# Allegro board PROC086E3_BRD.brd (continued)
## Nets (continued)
AOUT4_C: C197.1 R288.1 U33.6(-INB)
AOUT4_D: C199.1 R293.1 U33.5(+INB)
AOUT4_E: C199.2 R286.2 R289.1 R291.2
AOUT4_N: C202.2 TP65.1(TP) U32.26(VOUT4-)
AOUT4_O: C197.2 R287.2 R290.1 U33.7(OUTB)
AOUT4_P: C198.2 TP64.1(TP) U32.25(VOUT4+)
AOUT4N: C202.1 R295.1
AOUT4P: C198.1 R292.1
AOUT5_A: C362.1 R483.2 R484.1 R494.1 R496.2
AOUT5_B: C362.2 R492.1 R493.2 R494.2 R495.2
AOUT5_C: C360.1 R483.1 U56.2(-INA)
AOUT5_D: C363.1 R495.1 U56.3(+INA)
AOUT5_E: C363.2 R482.2 R487.1 R492.2
AOUT5_N: C364.2 U32.24(VOUT5-)
AOUT5_O: C360.2 R484.2 R488.1 U56.1(OUTA)
AOUT5_P: C361.2 U32.23(VOUT5+)
AOUT5N: C364.1 R496.1
AOUT5P: C361.1 R493.1
AOUT6_A: C370.1 R505.1 R507.2 R508.1 R509.2
AOUT6_B: C370.2 R502.1 R503.2 R505.2 R506.2
AOUT6_C: C367.1 R507.1 U56.6(-INB)
AOUT6_D: C371.1 R506.1 U56.5(+INB)
AOUT6_E: C371.2 R499.2 R501.1 R502.2
AOUT6_N: C372.2 U32.22(VOUT6-)
AOUT6_O: C367.2 R504.1 R508.2 U56.7(OUTB)
AOUT6_P: C368.2 U32.21(VOUT6+)
AOUT6N: C372.1 R509.1
AOUT6P: C368.1 R503.1
AOUT7_A: C187.1 R282.1 R283.1 R284.2 R285.2
AOUT7_B: C187.2 R275.1 R279.2 R281.2 R282.2
AOUT7_C: C184.1 R284.1 U31.2(-INA)
AOUT7_D: C186.1 R281.1 U31.3(+INA)
AOUT7_E: C186.2 R268.2 R273.1 R275.2
AOUT7_N: C189.2 TP66.1(TP) U32.20(VOUT7-)
AOUT7_O: C184.2 R280.1 R283.2 U31.1(OUTA)
AOUT7_P: C185.2 TP67.1(TP) U32.19(VOUT7+)
AOUT7N: C189.1 R285.1
AOUT7P: C185.1 R279.1
AOUT8_A: C173.1 R252.1 R253.2 R262.1 R265.2
AOUT8_B: C173.2 R258.1 R259.2 R261.2 R262.2
AOUT8_C: C169.1 R253.1 U31.6(-INB)
AOUT8_D: C172.1 R261.1 U31.5(+INB)
AOUT8_E: C172.2 R250.2 R254.1 R258.2
AOUT8_N: C177.2 TP69.1(TP) U32.18(VOUT8-)
AOUT8_O: C169.2 R252.2 R255.1 U31.7(OUTB)
AOUT8_P: C170.2 TP68.1(TP) U32.17(VOUT8+)
AOUT8N: C177.1 R265.1
AOUT8P: C170.1 R259.1
APP_BD_PORZ: J17.76 R486.1
AUD_REFCLK1_BUF: R122.2 U14.4(A2)
AUDEXP_INTB: J2.15 R103.2 TP123.1(TP) U15.22(I\N\T\)
AUDEXP_P16: TP54.1(TP) U15.16(P16)
AUDIO_EXT_REFCLK1: J1.26 R122.1 TP137.1(TP)
BIN1_N: C104.2 R172.2 R173.2 R179.2 TP71.1(TP) U19.51(VIN1-)
BIN1_P: C104.1 R184.2 R186.2 TP70.1(TP) U19.52(VIN1+)
BIN2_N: C120.2 R189.2 R191.2 R198.2 TP72.1(TP) U19.53(VIN2-)
BIN2_P: C120.1 R203.2 R204.2 TP73.1(TP) U19.54(VIN2+)
BIN3_N: C323.2 R429.2 R431.2 R439.2 U19.55(VIN3-)
BIN3_P: C323.1 R443.2 R444.2 U19.56(VIN3+)
BIN4_N: C308.2 R416.2 R417.2 R422.2 U19.57(VIN4-)
BIN4_P: C308.1 R426.2 R428.2 U19.58(VIN4+)
BIN5_N: C335.1 R452.2 R455.2 R456.2 TP76.1(TP) U19.61(VIN5-)
BIN5_P: C335.2 R450.2 R451.2 TP75.1(TP) U19.62(VIN5+)
BIN6_N: C125.1 R201.2 R202.2 R205.2 TP74.1(TP) U19.63(VIN6-)
BIN6_P: C125.2 R207.2 R209.2 TP77.1(TP) U19.64(VIN6+)
BISTEN: R7.1 U2.44(BISTEN)
BOUT1_A: C295.1 R395.2 R396.1 R401.1 R403.2
BOUT1_B: C295.2 R399.1 R400.2 R401.2 R402.2
BOUT1_C: C292.1 R395.1 U47.2(-INA)
BOUT1_D: C296.1 R402.1 U47.3(+INA)
BOUT1_E: C296.2 R392.2 R397.1 R399.2
BOUT1_N: C297.2 U19.32(VOUT1-)
BOUT1_O: C292.2 R396.2 R398.1 U47.1(OUTA)
BOUT1_P: C294.2 U19.31(VOUT1+)
BOUT1N: C297.1 R403.1
BOUT1P: C294.1 R400.1
BOUT2_A: C304.1 R410.1 R413.2 R414.1 R415.2
BOUT2_B: C304.2 R408.1 R409.2 R410.2 R411.2
BOUT2_C: C300.1 R413.1 U47.6(-INB)
BOUT2_D: C305.1 R411.1 U47.5(+INB)
BOUT2_E: C305.2 R405.2 R407.1 R408.2
BOUT2_N: C306.2 U19.30(VOUT2-)
BOUT2_O: C300.2 R412.1 R414.2 U47.7(OUTB)
BOUT2_P: C302.2 U19.29(VOUT2+)
BOUT2N: C306.1 R415.1
BOUT2P: C302.1 R409.1
BOUT3_A: C92.1 R164.1 R168.1 R169.2 R170.2
BOUT3_B: C92.2 R160.1 R162.2 R163.2 R164.2
BOUT3_C: C88.1 R169.1 U18.2(-INA)
BOUT3_D: C91.1 R163.1 U18.3(+INA)
BOUT3_E: C91.2 R153.2 R156.1 R160.2
BOUT3_N: C96.2 TP79.1(TP) U19.28(VOUT3-)
BOUT3_O: C88.2 R165.1 R168.2 U18.1(OUTA)
BOUT3_P: C90.2 TP78.1(TP) U19.27(VOUT3+)
BOUT3N: C96.1 R170.1
BOUT3P: C90.1 R162.1
BOUT4_A: C76.1 R140.1 R141.2 R149.1 R150.2
BOUT4_B: C76.2 R145.1 R147.2 R148.2 R149.2
BOUT4_C: C71.1 R141.1 U18.6(-INB)
BOUT4_D: C75.1 R148.1 U18.5(+INB)
BOUT4_E: C75.2 R139.2 R142.1 R145.2
BOUT4_N: C81.2 TP81.1(TP) U19.26(VOUT4-)
BOUT4_O: C71.2 R140.2 R143.1 U18.7(OUTB)
BOUT4_P: C73.2 TP80.1(TP) U19.25(VOUT4+)
BOUT4N: C81.1 R150.1
BOUT4P: C73.1 R147.1
BOUT5_A: C282.1 R369.2 R370.1 R377.1 R379.2
BOUT5_B: C282.2 R373.1 R375.2 R377.2 R378.2
BOUT5_C: C280.1 R369.1 U46.2(-INA)
BOUT5_D: C283.1 R378.1 U46.3(+INA)
BOUT5_E: C283.2 R368.2 R371.1 R373.2
BOUT5_N: C284.2 U19.24(VOUT5-)
BOUT5_O: C280.2 R370.2 R372.1 U46.1(OUTA)
BOUT5_P: C281.2 U19.23(VOUT5+)
BOUT5N: C284.1 R379.1
BOUT5P: C281.1 R375.1
BOUT6_A: C289.1 R387.1 R389.2 R390.1 R391.2
BOUT6_B: C289.2 R384.1 R385.2 R387.2 R388.2
BOUT6_C: C287.1 R389.1 U46.6(-INB)
BOUT6_D: C290.1 R388.1 U46.5(+INB)
BOUT6_E: C290.2 R381.2 R383.1 R384.2
BOUT6_N: C291.2 U19.22(VOUT6-)
BOUT6_O: C287.2 R386.1 R390.2 U46.7(OUTB)
BOUT6_P: C288.2 U19.21(VOUT6+)
BOUT6N: C291.1 R391.1
BOUT6P: C288.1 R385.1
BOUT7_A: C68.1 R135.1 R136.1 R137.2 R138.2
BOUT7_B: C68.2 R131.1 R132.2 R134.2 R135.2
BOUT7_C: C65.1 R137.1 U16.2(-INA)
BOUT7_D: C67.1 R134.1 U16.3(+INA)
BOUT7_E: C67.2 R127.2 R129.1 R131.2
BOUT7_N: C69.2 TP82.1(TP) U19.20(VOUT7-)
BOUT7_O: C65.2 R133.1 R136.2 U16.1(OUTA)
BOUT7_P: C66.2 TP83.1(TP) U19.19(VOUT7+)
BOUT7N: C69.1 R138.1
BOUT7P: C66.1 R132.1
BOUT8_A: C57.1 R106.1 R107.2 R115.1 R117.2
BOUT8_B: C57.2 R111.1 R113.2 R114.2 R115.2
BOUT8_C: C53.1 R107.1 U16.6(-INB)
BOUT8_D: C56.1 R114.1 U16.5(+INB)
BOUT8_E: C56.2 R105.2 R108.1 R111.2
BOUT8_N: C59.2 TP85.1(TP) U19.18(VOUT8-)
BOUT8_O: C53.2 R106.2 R109.1 U16.7(OUTB)
BOUT8_P: C55.2 TP84.1(TP) U19.17(VOUT8+)
BOUT8N: C59.1 R117.1
BOUT8P: C55.1 R113.1
BUF_VPFE0_DATA0: R37.2 U6.2(1B1) U6.13(2B1)
BUF_VPFE0_DATA1: R38.2 U6.3(1B2) U6.14(2B2)
BUF_VPFE0_DATA2: R33.2 U6.5(1B3) U6.16(2B3)
BUF_VPFE0_DATA3: R34.2 U6.6(1B4) U6.17(2B4)
BUF_VPFE0_DATA4: R39.2 U6.8(1B5) U6.19(2B5)
BUF_VPFE0_DATA5: R40.2 U6.9(1B6) U6.20(2B6)
BUF_VPFE0_DATA6: R35.2 U6.11(1B7) U6.22(2B7)
BUF_VPFE0_DATA7: R36.2 U6.12(1B8) U6.23(2B8)
BUF_VPFE0_DATA8: R45.2 U7.2(1B1) U7.13(2B1)
BUF_VPFE0_DATA9: R46.2 U7.3(1B2) U7.14(2B2)
BUF_VPFE0_DATA10: R41.2 U7.5(1B3) U7.16(2B3)
BUF_VPFE0_DATA11: R42.2 U7.6(1B4) U7.17(2B4)
BUF_VPFE0_DATA12: R532.2 U7.8(1B5)
BUF_VPFE0_DATA13: R533.2 U7.9(1B6)
BUF_VPFE0_HD: R43.2 U7.11(1B7) U7.22(2B7)
BUF_VPFE0_PCLK: R31.2 U5.11(2B1) U5.13(1B1)
BUF_VPFE0_VD: R44.2 U7.12(1B8) U7.23(2B8)
C_FPD_DOUT_N: C36.1 U8.19(DOUT-)
C_FPD_DOUT_P: C37.1 U8.20(DOUT+)
C_FPD_RIN_N: C17.1 U2.50(RIN-)
C_FPD_RIN_P: C16.1 U2.49(RIN+)
CAM_EXT_CLK: U35.2(1A) U35.5(2A) U38.3(OUTPUT)
CAM_I2C_SCL: J3.14 J6.29 R317.2 U36.3(SCL1)
CAM_I2C_SDA: J3.12 J6.30 R316.2 U36.4(SDA1)
CAM_LI_EXT_CLK: J6.7 R323.2
CAM_OV_EXT_CLK: J3.20 R315.2
CAM_SEL_LI#: U3.15(1\O\E\) U4.14(2\O\E\) U4.15(1\O\E\) U5.15(1\O\E\) U6.48(1O\E\) U7.48(1O\E\) U39.4(Y)
CAM_SEL_OV#: J1.91 TP135.1(TP) U3.14(2\O\E\) U5.14(2\O\E\) U6.25(2O\E\) U7.25(2O\E\) U39.2(A)
CAM_VIO_SEL: J2.20 U1.1(EN1)
CAPI2S: C24.1 U2.58(CAPI2S)
CAPL12: C26.1 C229.1 U2.4(CAPL12)
CAPP12: C23.1 U2.57(CAPP12)
CAPR12: C21.1 U2.55(CAPR12)
CDCE_1V8_I2C_SCL: R68.2 U9.3(SCL1) U42.12(SCL/S2)
CDCE_1V8_I2C_SDA: R69.2 U9.4(SDA1) U42.13(SDA/S1)
CDCE_PCLK: R22.2 R23.1 TP136.1(TP) U42.1(XIN/CLK)
CDCE_S0: R339.2 R342.1 U42.2(S0)
CDCE_VCTR: R54.2 U42.4(VCTR)
CDCE_Y1: R27.1 R63.1
CMC_FPD_DOUT_N: C36.2 FL5.2
CMC_FPD_DOUT_P: C37.2 FL5.1
CMC_FPD_RIN_N: C17.2 FL3.1
CMC_FPD_RIN_P: C16.2 FL3.2
CMF: C18.1 U2.51(CMF)
CODEC1_ACLKX: R188.2 U32.7(BCKAD) U32.36(BCKDA)
CODEC1_I2C_ADD0: R271.1 R272.2 U32.45(MS/ADR0/MD0)
CODEC1_I2C_ADD1: R277.1 R278.2 U32.44(MDO/ADR1/MD1)
CODEC1_MODE: R263.2 R264.2 U32.48(MODE)
CODEC1_OVF: TP13.1(TP) U32.5(OVF)
CODEC1_SCKI: R215.2 U32.41(SCKI)
CODEC1_VREFAD1: C157.1 U32.59(VREFAD1)
CODEC1_VREFAD2: C161.1 U32.60(VREFAD2)
CODEC1_ZERO: TP14.1(TP) U32.13(ZERO)
CODEC2_ACLKX: R187.2 U19.7(BCKAD) U19.36(BCKDA)
CODEC2_I2C_ADD0: R166.2 R167.1 U19.45(MS/ADR0/MD0)
CODEC2_I2C_ADD1: R158.2 R159.1 U19.44(MDO/ADR1/MD1)
CODEC2_MODE: R171.2 R174.2 U19.48(MODE)
CODEC2_OVF: TP3.1(TP) U19.5(OVF)
CODEC2_SCKI: R214.2 U19.41(SCKI)
CODEC2_VREFAD1: C312.1 U19.59(VREFAD1)
CODEC2_VREFAD2: C311.1 U19.60(VREFAD2)
CODEC2_ZERO: TP2.1(TP) U19.13(ZERO)
CODEC_RESETN: R498.1 TP102.1(TP) U15.1(P00) U19.4(RST#) U32.4(RST#)
CODEC_SCKI: J2.16 R538.1
CODECA_LIN_L: C332.2 J15.5B
CODECA_LIN_L_AC: C332.1 R449.1
CODECA_LIN_R: C134.2 J15.2B
CODECA_LIN_R_AC: C134.1 R210.1
CODECA_MIC1_L: J16.5B R227.1 R232.1
CODECA_MIC1_R: J16.2B R237.1 R245.1
CODECA_MIC2_L: J16.5A R470.1 R478.1
CODECA_MIC2_R: J16.2A R460.1 R467.1
CODECA_VOUT1: C373.2 J19.5B R520.1
CODECA_VOUT2: C380.2 J19.2B R522.1
CODECA_VOUT3: C204.2 J19.5A R300.1
CODECA_VOUT4: C196.2 J19.2A R296.1
CODECA_VOUT5: C359.2 J18.5B R497.1
CODECA_VOUT6: C366.2 J18.2B R500.1
CODECA_VOUT7: C183.2 J18.5A R269.1
CODECA_VOUT8: C168.2 J18.2A R266.1
CODECB_LIN_L: C338.2 J15.5A
CODECB_LIN_L_AC: C338.1 R457.1
CODECB_LIN_R: C122.2 J15.2A
CODECB_LIN_R_AC: C122.1 R200.1
CODECB_MIC1_L: J13.5B R178.1 R185.1
CODECB_MIC1_R: J13.2B R190.1 R197.1
CODECB_MIC2_L: J13.5A R430.1 R436.1
CODECB_MIC2_R: J13.2A R419.1 R427.1
CODECB_VOUT1: C293.2 J12.5B R404.1
CODECB_VOUT2: C301.2 J12.2B R406.1
CODECB_VOUT3: C89.2 J12.5A R155.1
CODECB_VOUT4: C72.2 J12.2A R151.1
CODECB_VOUT5: C279.2 J11.5B R380.1
CODECB_VOUT6: C286.2 J11.2B R382.1
CODECB_VOUT7: C64.2 J11.5A R128.1
CODECB_VOUT8: C52.2 J11.2A R118.1
CON_UB921_INTB: J1.87 R65.2
CON_VPFE0_DATA6: J1.22 U10.13(6A)
CON_VPFE0_DATA7: J1.24 U10.15(7A)
CON_VPFE0_DATA11: J1.56 U10.18(8A)
CON_VPFE0_DATA12: J1.54 U10.21(9A)
CONN_HDMI1_CEC: J4.13(CEC) U34.7(CEC_B)
CONN_HDMI1_CLK_N: FL19.3 J4.12(CLKN) U34.15(CLK-)
CONN_HDMI1_CLK_P: FL19.4 J4.10(CLKP) U34.16(CLK+)
CONN_HDMI1_HPD: J4.19(HPD) U34.10(HPD_B)
CONN_HDMI1_SCL: D1.1(CATHODE) J4.15(SCL) R319.2 U37.6(SCL2)
CONN_HDMI1_SDA: D2.1(CATHODE) J4.16(SDA) R320.2 U37.5(SDA2)
CONN_HDMI1_TXD0_N: FL18.3 J4.9(DATA0N) U34.17(D0-)
CONN_HDMI1_TXD0_P: FL18.4 J4.7(DATA0P) U34.18(D0+)
CONN_HDMI1_TXD1_N: FL17.3 J4.6(DATA1N) U34.20(D1-)
CONN_HDMI1_TXD1_P: FL17.4 J4.4(DATA1P) U34.21(D1+)
CONN_HDMI1_TXD2_N: FL16.3 J4.3(DATA2N) U34.22(D2-)
CONN_HDMI1_TXD2_P: FL16.4 J4.1(DATA2P) U34.23(D2+)
CT_HPD: R322.1 U34.12(CT_HPD)
DIR_AUDIO#: Q1.1(GATE) U45.1(A\U\D\I\O\)
DIR_BCKO: U14.17(B5) U14.18(B4) U45.11(BCKO)
DIR_BFRAME: TP47.1(TP) U45.18(BFRAME)
DIR_CKSEL: R351.2 R352.1 R355.2 TP111.1(TP) U15.11(P11) U45.28(CKSEL)
DIR_CLKST: TP48.1(TP) U45.9(CLKST)
DIR_COUT: TP50.1(TP) U45.15(COUT)
DIR_DOUT: U14.21(B1) U45.12(DOUT)
DIR_EMPH: Q3.1(GATE) U45.17(EMPH)
DIR_ERROR: Q2.1(GATE) R355.1 U45.27(ERROR)
DIR_FILT: C277.1 R101.1 U45.22(FILT)
DIR_FMT0: R97.2 R360.1 TP112.1(TP) U15.12(P12) U45.25(FMT0)
DIR_FMT1: R96.2 R357.1 TP113.1(TP) U15.13(P13) U45.26(FMT1)
DIR_JACK: C47.2 J8.2 R102.1
DIR_JACK_AC: C47.1 R100.2 U13.1(A)
DIR_LRCKO: U14.14(B8) U14.15(B7) U45.10(LRCKO)
DIR_PSCK0: R363.1 R365.2 TP114.1(TP) U15.14(P14) U45.13(PSCK0)
DIR_PSCK1: R364.1 R366.2 TP115.1(TP) U15.15(P15) U45.14(PSCK1)
DIR_RESETN: R98.2 TP110.1(TP) U15.10(P10) U45.21(R\S\T\)
DIR_RSV: R361.1 U45.19(RSV)
DIR_RXIN: SW1.2(COM) U45.20(RXIN)
DIR_RXIN_COAX: SW1.1 U13.4(Y)
DIR_SCKO: U14.20(B2) U45.4(SCKO)
DIR_UOUT: TP49.1(TP) U45.16(UOUT)
DIR_XTI: C276.1 U45.8(XTI) Y1.1
DIR_XTO: R359.1 U45.7(XTO)
DIT_GND: J9.1 J9.3 R116.2
DIT_JACK: J9.2 R104.2
DIT_JACK_AC: C51.1 R112.1 R119.2
EEPROM_A0: J2.19 R251.2 U30.1(A0)
EEPROM_A1: J2.21 R249.2 U30.2(A1)
EEPROM_A2: J2.23 R246.2 U30.3(A2)
EEPROM_WP: J2.25 R248.2 U30.7(WP)
EXP_3V3: J2.2 J2.4 J2.6 R260.2
EXP_DC_3V3: J17.57 J17.58 J17.59 J17.60 R473.2 R475.2
EXP_I2C1_SCL: J17.30 R218.2
EXP_I2C1_SDA: J17.28 R216.2
EXP_I2C2_SCL: J20.22 R310.2
EXP_I2C2_SDA: J20.21 R298.2
EXP_I2C4_SCL: J14.11 R434.2
EXP_I2C4_SDA: J14.12 R446.2
EXP_REFCLK: J2.22 TP11.1(TP)
EXP_RSTZ: J1.118 TP51.1(TP)
FPD_DE: TP141.1(TP) U8.5(DE) U10.7(3B3)
FPD_DOUT_N: FL5.3 J7.3
FPD_DOUT_P: FL5.4 J7.1
FPD_HSYNC: TP140.1(TP) U8.3(HS) U10.5(2B3)
FPD_PCLK: R22.1 R26.1 TP139.1(TP) U10.28(12B3)
FPD_RIN_N: FL3.4 J5.2
FPD_RIN_P: FL3.3 J5.4
FPD_VSYNC: TP142.1(TP) U8.4(VS) U10.10(4B3)
FSOUT0: TP42.1(TP) U45.2(FSOUT0)
FSOUT1: TP43.1(TP) U45.3(FSOUT1)
GPIO0_31: TP131.1(TP) U4.13(1B1) U11.31(11B2)
GPIO0_32: TP132.1(TP) U3.11(2B1) U3.12(1B2) U11.29(12B2)
HDMI1_CEC: TP25.1(TP) U34.1(CEC_A)
HDMI1_CLK_N: FL19.2 U41.21(TXC-)
HDMI1_CLK_P: FL19.1 U41.22(TXC+)
HDMI1_CTL1: R49.1 R343.2 U41.8(CTL1/A1/DK1)
HDMI1_CTL2: R52.1 R344.2 U41.7(CLT2/A2/DK2)
HDMI1_CTL3: R53.1 R345.2 U41.6(CLT3/A3/DK3)
HDMI1_DATA0: R72.2 U41.63(DATA0)
HDMI1_DATA0_R: R72.1 U11.54(1B1)
HDMI1_DATA1: R73.2 U41.62(DATA1)
HDMI1_DATA1_R: R73.1 U11.52(2B1)
HDMI1_DATA2: R74.2 U41.61(DATA2)
HDMI1_DATA2_R: R74.1 U11.50(3B1)
HDMI1_DATA3: R75.2 U41.60(DATA3)
HDMI1_DATA3_R: R75.1 U11.47(4B1)
HDMI1_DATA4: R76.2 U41.59(DATA4)
HDMI1_DATA4_R: R76.1 U11.45(5B1)
HDMI1_DATA5: R77.2 U41.58(DATA5)
HDMI1_DATA5_R: R77.1 U11.43(6B1)
HDMI1_DATA6: R78.2 U41.55(DATA6)
HDMI1_DATA6_R: R78.1 U11.41(7B1)
HDMI1_DATA7: R79.2 U41.54(DATA7)
HDMI1_DATA7_R: R79.1 U11.39(8B1)
HDMI1_DATA8: R80.2 U41.53(DATA8)
HDMI1_DATA8_R: R80.1 U11.36(9B1)
HDMI1_DATA9: R81.2 U41.52(DATA9)
HDMI1_DATA9_R: R81.1 U11.34(10B1)
HDMI1_DATA10: R82.2 U41.51(DATA10)
HDMI1_DATA10_R: R82.1 U11.32(11B1)
HDMI1_DATA11: R83.2 U41.50(DATA11)
HDMI1_DATA11_R: R83.1 U11.30(12B1)
HDMI1_DATA12: R84.2 U41.47(DATA12)
HDMI1_DATA12_R: R84.1 U12.54(1B1)
HDMI1_DATA13: R85.2 U41.46(DATA13)
HDMI1_DATA13_R: R85.1 U12.52(2B1)
HDMI1_DATA14: R86.2 U41.45(DATA14)
HDMI1_DATA14_R: R86.1 U12.50(3B1)
HDMI1_DATA15: R87.2 U41.44(DATA15)
HDMI1_DATA15_R: R87.1 U12.47(4B1)
HDMI1_DATA16: R88.2 U41.43(DATA16)
HDMI1_DATA16_R: R88.1 U12.45(5B1)
HDMI1_DATA17: R89.2 U41.42(DATA17)
HDMI1_DATA17_R: R89.1 U12.43(6B1)
HDMI1_DATA18: R90.2 U41.41(DATA18)
HDMI1_DATA18_R: R90.1 U12.41(7B1)
HDMI1_DATA19: R91.2 U41.40(DATA19)
HDMI1_DATA19_R: R91.1 U12.39(8B1)
HDMI1_DATA20: R92.2 U41.39(DATA20)
HDMI1_DATA20_R: R92.1 U12.36(9B1)
HDMI1_DATA21: R93.2 U41.38(DATA21)
HDMI1_DATA21_R: R93.1 U12.34(10B1)
HDMI1_DATA22: R94.2 U41.37(DATA22)
HDMI1_DATA22_R: R94.1 U12.32(11B1)
HDMI1_DATA23: R95.2 U41.36(DATA23)
HDMI1_DATA23_R: R95.1 U12.30(12B1)
HDMI1_DE: R61.2 TP36.1(TP) U41.2(DE)
HDMI1_DE_R: R61.1 U10.50(3B1)
HDMI1_DKEN: R29.2 R335.1 U41.35(DKEN)
HDMI1_HSYNC: R60.2 TP37.1(TP) U41.4(HSYNC)
HDMI1_HSYNC_R: R60.1 U10.52(2B1)
HDMI1_ISEL: C251.1 R32.2 R337.1 U41.13(ISEL/R\S\T\)
HDMI1_PCLK: R67.2 TP40.1(TP) U41.57(IDCK+)
HDMI1_PCLK_R: R67.1 U10.30(12B1)
HDMI1_TXD0_N: FL18.2 U41.24(TX0-)
HDMI1_TXD0_P: FL18.1 U41.25(TX0+)
HDMI1_TXD1_N: FL17.2 U41.27(TX1-)
HDMI1_TXD1_P: FL17.1 U41.28(TX1+)
HDMI1_TXD2_N: FL16.2 U41.30(TX2-)
HDMI1_TXD2_P: FL16.1 U41.31(TX2+)
HDMI1_VSYNC: R57.2 TP35.1(TP) U41.5(VSYNC)
HDMI1_VSYNC_R: R57.1 U10.47(4B1)
HDMI_BSEL: R25.1 R333.2 U41.15(BSEL/SCL)
HDMI_DDC_OE: R328.1 TP118.1(TP) U34.5(LS_OE) U37.8(EN) U43.11(P11)
HDMI_DSEL: R28.1 R334.2 U41.14(DSEL/SDA)
HDMI_EDGE: R48.1 R341.2 U41.9(EDGE/HTPLG)
HDMI_HPD: TP119.1(TP) U34.4(HPD_A) U43.12(P12)
HDMI_PDN: R340.2 TP117.1(TP) U41.10(P\D\) U43.10(P10)
HDMI_TFADJ: R21.2 U41.19(TFADJ)
HDMI_VREF: R346.1 U41.3(VREF)
I2C0_SCL: J1.109 TP55.1(TP)
I2C0_SDA: J1.111 TP56.1(TP)
I2C1_SCL: J1.113 R50.2 R376.2 TP133.1(TP) U8.8(SCL) U37.3(SCL1) U43.19(SCL)
I2C1_SDA: J1.115 R51.2 R374.2 TP134.1(TP) U8.9(SDA) U37.4(SDA1) U43.20(SDA)
I2C3_SCL: J2.8 R434.1 R491.1 TP129.1(TP) U2.3(SCL) U15.19(SCL) U19.42(MC/SCL/FMT) U32.42(MC/SCL/FMT)
I2C3_SDA: J2.10 R446.1 R485.1 TP130.1(TP) U2.2(SDA) U15.20(SDA) U19.43(MDI/SDA/DEMP) U32.43(MDI/SDA/DEMP)
I2C6_SCL: J2.107 R208.2 TP127.1(TP) U36.6(SCL2)
I2C6_SDA: J2.109 R206.2 TP128.1(TP) U36.5(SDA2)
I2S_CLK: R18.2 U2.1(GPO_REG8/I2S_CLK)
IDCK#: R58.1 U41.56(IDCK-)
IO_EXP_RESETN: R144.1 R146.1 TP138.1(TP) U15.24(R\E\S\E\T\) U43.24(R\E\S\E\T\)
JAMR3_GPIO0: J1.17 J14.33
JAMR3_GPIO1: J1.9 J14.34
JAMR3_GPIO2: J1.89 J14.35
JAMR3_I2S_CLK: J17.104 TP148.1(TP) U10.45(5B1)
JAMR3_I2S_DA: J17.103 TP150.1(TP) U10.34(10B1)
JAMR3_I2S_DB: J1.100 J17.105 TP151.1(TP)
JAMR3_I2S_WC: J17.102 TP149.1(TP) U10.32(11B1)
JAMR3_PWR_CTRL: R475.1 TP104.1(TP) U15.3(P02)
JAMR3_RESETN: J20.13 R297.1 TP103.1(TP) U15.2(P01)
LI_CAM_RST#: J6.33 R11.1 U3.5(1A2)
LI_CAM_TRIGGER: J6.35 R10.2 U4.4(1A1)
LI_SPI3_CLK: J6.32 U4.7(2A2)
LI_SPI3_CS0: J6.34 U4.6(2A1)
LI_SPI3_MISO: J6.31 U5.5(1A2)
LI_SPI3_MOSI: J6.36 U4.5(1A2)
LI_VIN_DATA0: J6.28 U6.47(1A1)
LI_VIN_DATA1: J6.27 U6.46(1A2)
LI_VIN_DATA2: J6.24 U6.44(1A3)
LI_VIN_DATA3: J6.23 U6.43(1A4)
LI_VIN_DATA4: J6.22 U6.41(1A5)
LI_VIN_DATA5: J6.21 U6.40(1A6)
LI_VIN_DATA6: J6.20 U6.38(1A7)
LI_VIN_DATA7: J6.19 U6.37(1A8)
LI_VIN_DATA8: J6.18 U7.47(1A1)
LI_VIN_DATA9: J6.17 U7.46(1A2)
LI_VIN_DATA10: J6.16 U7.44(1A3)
LI_VIN_DATA11: J6.15 U7.43(1A4)
LI_VIN_DATA12: J6.14 U7.41(1A5)
LI_VIN_DATA13: J6.13 U7.40(1A6)
LI_VIN_HD: J6.12 TP18.1(TP) U7.38(1A7)
LI_VIN_PCLK: R324.1 TP26.1(TP) U5.4(1A1)
LI_VIN_VD: J6.11 TP24.1(TP) U7.37(1A8)
LINA_L_A: C331.2 R447.1 U51.1(OUTA)
LINA_L_B: C331.1 R448.1 R449.2 U51.2(-INA)
LINA_L_C: C327.1 R441.1 R445.1 U51.6(-INB)
LINA_L_D: C327.2 R442.1 U51.7(OUTB)
LINA_R_A: C135.2 R212.1 U26.1(OUTA)
LINA_R_B: C135.1 R210.2 R211.1 U26.2(-INA)
LINA_R_C: C142.1 R217.1 R222.1 U26.6(-INB)
LINA_R_D: C142.2 R221.1 U26.7(OUTB)
LINB_L_A: C337.2 R455.1 U52.1(OUTA)
LINB_L_B: C337.1 R456.1 R457.2 U52.2(-INA)
LINB_L_C: C333.1 R450.1 R452.1 U52.6(-INB)
LINB_L_D: C333.2 R451.1 U52.7(OUTB)
LINB_R_A: C123.2 R202.1 U24.1(OUTA)
LINB_R_B: C123.1 R200.2 R201.1 U24.2(-INA)
LINB_R_C: C129.1 R205.1 R209.1 U24.6(-INB)
LINB_R_D: C129.2 R207.1 U24.7(OUTB)
MCASP0_ACLKX: J1.57 TP94.1(TP) U21.2(1A) U21.5(2A)
MCASP0_AFSX: J1.59 TP93.1(TP) U19.6(LRCKAD) U19.35(LRCKDA) U32.6(LRCKAD) U32.35(LRCKDA)
MCASP0_AXR0: J1.69 TP87.1(TP) U32.37(DIN1)
MCASP0_AXR1: J1.77 TP86.1(TP) U32.38(DIN2)
MCASP0_AXR2: J1.71 TP88.1(TP) U32.39(DIN3)
MCASP0_AXR3: J1.61 TP89.1(TP) U32.40(DIN4)
MCASP0_AXR4: J1.73 R270.2 TP90.1(TP)
MCASP0_AXR4_R: R270.1 U32.8(DOUT1)
MCASP0_AXR5: J1.53 R274.2 TP91.1(TP)
MCASP0_AXR5_R: R274.1 U32.9(DOUT2)
MCASP0_AXR6: J1.55 R276.2 TP92.1(TP)
MCASP0_AXR6_R: R276.1 U32.10(DOUT3)
MCASP0_AXR7: J1.72 TP95.1(TP) U19.37(DIN1)
MCASP0_AXR8: J1.70 TP96.1(TP) U19.38(DIN2)
MCASP0_AXR9: J1.78 TP97.1(TP) U19.39(DIN3)
MCASP0_AXR10: J1.76 TP98.1(TP) U19.40(DIN4)
MCASP0_AXR11: J1.74 R161.2 TP99.1(TP)
MCASP0_AXR11_R: R161.1 U19.8(DOUT1)
MCASP0_AXR12: J1.80 R157.2 TP100.1(TP)
MCASP0_AXR12_R: R157.1 U19.9(DOUT2)
MCASP0_AXR13: J1.102 R154.2 TP101.1(TP)
MCASP0_AXR13_R: R154.1 U19.10(DOUT3)
MCASP1_ACLKX: J1.110 R19.1 TP156.1(TP)
MCASP1_AFSX: J1.60 TP157.1(TP) U2.39(ROUT2/R2)
MCASP1_AXR0: J1.13 TP158.1(TP) U2.37(ROUT3/R3)
MCASP1_AXR1: J1.15 TP159.1(TP) U2.36(ROUT4/R4)
MCASP1_AXR2: J1.11 TP160.1(TP) U2.35(ROUT5/R5)
MCASP1_AXR3: J1.7 U2.34(ROUT6/R6)
MCASP1_AXR5: J2.7 U2.33(ROUT7/R7)
MCASP1_AXR6: J2.9 U2.26(ROUT10/G2)
MCASP1_AXR7: J1.85 U2.25(ROUT11/G3)
MCASP1_AXR8: J1.83 U2.23(ROUT12/G4)
MCASP2_AXR0: J1.93 R119.1
MCASP6_ACLKR: J1.92 R124.1
MCASP6_ACLKX: R123.1 U17.5(2B1)
MCASP6_AFSR: R126.1 R536.2
MCASP6_AFSX: R125.1 U17.11(3B1)
MCASP6_AXR0: R121.1 U17.2(1B1)
MCASP6_AXR1: TP1.1(TP) U17.14(4B1)
MCASP6_MUX_SEL: R130.2 TP116.1(TP) U15.17(P17) U17.1(S)
MCASP10_ACLKX/EHRPWM0_SYNCI: J2.41 J10.2
MCASP10_AFSX/EHRPWM0_SYNCO: J2.43 J10.3
MCASP10_AXR0/EHRPWM_TZN_IN0: J2.45 J10.4
MCASP10_AXR1/EHRPWM0_A: J2.47 J10.5
MCASP10_AXR2/EHRPWM1_B: J2.51 J10.6
MCASP10_AXR3/EHRPWM_TZN_IN1: J2.59 J10.1
MCASP11_ACLKX: J2.49 R235.2 TP143.1(TP)
MCASP11_AFSX: J2.53 R233.2 TP144.1(TP)
MCASP11_AXR0: J2.55 J17.37 TP145.1(TP)
MCASP11_AXR1: J2.61 J17.33 TP146.1(TP)
MCASP11_AXR2: J2.57 J17.39 TP147.1(TP)
MCASP11_AXR3: J2.63 J17.35
MCASP11_AXR4: J2.52 J17.23
MCASP11_AXR5: J2.42 J17.24
MCASP11_AXR6: J2.48 J17.22
MCASP11_AXR7: J2.44 J17.38
MCASP_ACLKR_BUF: R124.2 U14.7(A5)
MCASP_ACLKX_BUF: R123.2 U14.6(A4)
MCASP_AFSR_BUF: R126.2 U14.10(A8)
MCASP_AFSX_BUF: R125.2 U14.9(A7)
MCASP_AXR0_BUF: R121.2 U14.3(A1)
MIC1AL_A: C143.2 R219.1 U27.7(OUTB)
MIC1AL_AC: C147.1 R228.1
MIC1AL_B: C143.1 R220.1 R228.2 U27.6(-INB)
MIC1AL_BIAS: C151.2 R230.2 R232.2
MIC1AL_BIAS_AC: C148.1 C151.1 R229.1 U28.6(-INB)
MIC1AL_C: C150.1 R224.1 R231.1 U27.2(-INA)
MIC1AL_D: C150.2 R234.1 U27.1(OUTA)
MIC1AL_PRE: C148.2 R223.1 R229.2 U28.7(OUTB)
MIC1AR_A: C154.2 R236.1 U29.7(OUTB)
MIC1AR_AC: C158.1 R241.1
MIC1AR_B: C154.1 R238.1 R241.2 U29.6(-INB)
MIC1AR_BIAS: C153.2 R237.2 R239.2
MIC1AR_BIAS_AC: C153.1 C156.1 R240.1 U28.2(-INA)
MIC1AR_C: C163.1 R242.1 R256.1 U29.2(-INA)
MIC1AR_D: C163.2 R257.1 U29.1(OUTA)
MIC1AR_PRE: C156.2 R240.2 R247.1 U28.1(OUTA)
MIC1BL_A: C98.2 R172.1 U20.7(OUTB)
MIC1BL_AC: C105.1 R180.1
MIC1BL_B: C98.1 R173.1 R180.2 U20.6(-INB)
MIC1BL_BIAS: C111.2 R182.2 R185.2
MIC1BL_BIAS_AC: C106.1 C111.1 R181.1 U22.6(-INB)
MIC1BL_C: C108.1 R179.1 R184.1 U20.2(-INA)
MIC1BL_D: C108.2 R186.1 U20.1(OUTA)
MIC1BL_PRE: C106.2 R175.1 R181.2 U22.7(OUTB)
MIC1BR_A: C115.2 R189.1 U23.7(OUTB)
MIC1BR_AC: C118.1 R194.1
MIC1BR_B: C115.1 R191.1 R194.2 U23.6(-INB)
MIC1BR_BIAS: C114.2 R190.2 R192.2
MIC1BR_BIAS_AC: C114.1 C117.1 R193.1 U22.2(-INA)
MIC1BR_C: C121.1 R198.1 R203.1 U23.2(-INA)
MIC1BR_D: C121.2 R204.1 U23.1(OUTA)
MIC1BR_PRE: C117.2 R193.2 R199.1 U22.1(OUTA)
MIC2AL_A: C351.2 R469.1 U55.1(OUTA)
MIC2AL_AC: C354.1 R476.1
MIC2AL_B: C351.1 R471.1 R476.2 U55.2(-INA)
MIC2AL_BIAS: C350.2 R470.2 R472.2
MIC2AL_BIAS_AC: C350.1 C353.1 R474.1 U54.6(-INB)
MIC2AL_C: C358.1 R477.1 R489.1 U55.6(-INB)
MIC2AL_D: C358.2 R490.1 U55.7(OUTB)
MIC2AL_PRE: C353.2 R474.2 R481.1 U54.7(OUTB)
MIC2AR_A: C339.2 R453.1 U53.1(OUTA)
MIC2AR_AC: C342.1 R463.1
MIC2AR_B: C339.1 R454.1 R463.2 U53.2(-INA)
MIC2AR_BIAS: C347.2 R465.2 R467.2
MIC2AR_BIAS_AC: C343.1 C347.1 R464.1 U54.2(-INA)
MIC2AR_C: C345.1 R459.1 R466.1 U53.6(-INB)
MIC2AR_D: C345.2 R468.1 U53.7(OUTB)
MIC2AR_PRE: C343.2 R458.1 R464.2 U54.1(OUTA)
MIC2BL_A: C319.2 R429.1 U50.1(OUTA)
MIC2BL_AC: C322.1 R435.1
MIC2BL_B: C319.1 R431.1 R435.2 U50.2(-INA)
MIC2BL_BIAS: C318.2 R430.2 R432.2
MIC2BL_BIAS_AC: C318.1 C321.1 R433.1 U49.6(-INB)
MIC2BL_C: C326.1 R439.1 R443.1 U50.6(-INB)
MIC2BL_D: C326.2 R444.1 U50.7(OUTB)
MIC2BL_PRE: C321.2 R433.2 R440.1 U49.7(OUTB)
MIC2BR_A: C307.2 R416.1 U48.1(OUTA)
MIC2BR_AC: C310.1 R423.1
MIC2BR_B: C307.1 R417.1 R423.2 U48.2(-INA)
MIC2BR_BIAS: C316.2 R425.2 R427.2
MIC2BR_BIAS_AC: C313.1 C316.1 R424.1 U49.2(-INA)
MIC2BR_C: C315.1 R422.1 R426.1 U48.6(-INB)
MIC2BR_D: C315.2 R428.1 U48.7(OUTB)
MIC2BR_PRE: C313.2 R418.1 R424.2 U49.1(OUTA)
MODE_SEL: R16.1 R17.2 U2.15(MODE_SEL)
MUX_MCASP6_ACLKX: J1.84 TP153.1(TP) U17.7(2A)
MUX_MCASP6_AFSX: J1.88 TP154.1(TP) U17.9(3A)
MUX_MCASP6_AXR0: J1.94 TP152.1(TP) U17.4(1A)
MUX_MCASP6_AXR1: J1.90 TP155.1(TP) U17.12(4A)
OEN: R8.1 U2.31(OEN)
OSS_SEL: R6.1 U2.46(OSS_SEL)
OV_CAM_PWDN: R318.2 U3.6(2A1)
OV_VIN_DATA0: J3.26 U6.36(2A1)
OV_VIN_DATA1: J3.25 U6.35(2A2)
OV_VIN_DATA2: J3.24 U6.33(2A3)
OV_VIN_DATA3: J3.23 U6.32(2A4)
OV_VIN_DATA4: J3.2 U6.30(2A5)
OV_VIN_DATA5: J3.1 U6.29(2A6)
OV_VIN_DATA6: J3.4 U6.27(2A7)
OV_VIN_DATA7: J3.3 U6.26(2A8)
OV_VIN_DATA8: J3.6 U7.36(2A1)
OV_VIN_DATA9: J3.5 U7.35(2A2)
OV_VIN_DATA10: J3.8 U7.33(2A3)
OV_VIN_DATA11: J3.7 U7.32(2A4)
OV_VIN_HD: J3.13 TP16.1(TP) U7.27(2A7)
OV_VIN_PCLK: R312.1 TP17.1(TP) U5.6(2A1)
OV_VIN_PCLK_R: J3.17 R312.2
OV_VIN_VD: J3.15 TP15.1(TP) U7.26(2A8)
PCLK_R: R26.2 R27.2 U8.10(PCLK)
PERIPH_RSTZ: J2.28 R146.2
PWR_SW_UB921: R71.1 TP121.1(TP) U43.14(P14) U44.3(IN)
PWR_SW_UB926: R331.1 TP106.1(TP) U15.5(P04) U40.3(IN)
R_CDCE_Y1: R63.2 U42.11(Y1)
R_CODEC1_ACLKX: R188.1 U21.6(1Y)
R_CODEC1_SCKI: R215.1 U25.6(1Y)
R_CODEC2_ACLKX: R187.1 U21.3(2Y)
R_CODEC2_SCKI: R214.1 U25.3(2Y)
R_DIR_XTO: C267.1 R359.2 Y1.2
R_LI_VIN_PCLK: J6.9 R324.2
R_OV_CAM_PWDN: J3.10 R311.1 R313.2 R318.1
REFCLK0: R537.2 R539.1
REFCLK0/MCASP6_AFSR: J1.86 R536.1 R537.1
REFCLK0/REFCLK2: R538.2 R539.2 TP9.1(TP) U25.2(1A) U25.5(2A)
RESETSTATZ: J2.30 TP10.1(TP)
RXIN_OPTICAL: MOD1.3(VOUT) SW1.3
SHLD_GND_HDMI1: FL13.2 J4.20 J4.21 J4.22 J4.23
SOC_I2C2_SCL: J1.112 TP53.1(TP)
SOC_I2C2_SDA: J1.114 TP52.1(TP)
SOC_PORZ_OUT: J1.64 R144.2
SPI3_CLK: J1.105 U10.23(10A)
SPI3_CLK_MUX: U4.10(2B2) U10.33(10B2)
SPI3_CS0: J1.58 U4.11(2B1)
SPI3_D0: J1.101 U10.25(11A)
SPI3_D1: J1.103 U10.11(5A)
SPI3_MISO: U5.12(1B2) U10.44(5B2)
SPI3_MOSI: U4.12(1B2) U10.31(11B2)
U37_CL: R332.1 U40.13(CL)
U37_DIAG_EN: R330.1 U40.12(DIAG_EN)
U66_CL: R353.1 U44.13(CL)
U66_DIAG_EN: R349.1 U44.12(DIAG_EN)
UB921_DIN0: U8.43(GPO_REG4/B0/DIN16) U11.3(1B3)
UB921_DIN1: U8.44(GPO_REG5/B1/DIN17) U11.5(2B3)
UB921_DIN2: U8.45(B2/DIN18) U11.7(3B3)
UB921_DIN3: U8.46(B3/DIN19) U11.10(4B3)
UB921_DIN4: U8.47(B4/DIN20) U11.12(5B3)
UB921_DIN5: U8.48(B5/DIN21) U11.14(6B3)
UB921_DIN6: U8.1(B6/DIN22) U11.16(7B3)
UB921_DIN7: U8.2(B7/DIN23) U11.20(8B3)
UB921_DIN8: U8.35(DIN8/G0/GPIO2) U11.22(9B3)
UB921_DIN9: U8.36(DIN9/G1/GPIO3) U11.24(10B3)
UB921_DIN10: U8.37(G2/DIN10) U11.26(11B3)
UB921_DIN11: U8.38(G3 / DIN11) U11.28(12B3)
UB921_DIN12: U8.39(G4/DIN12) U12.3(1B3)
UB921_DIN13: U8.40(G5/DIN13) U12.5(2B3)
UB921_DIN14: U8.41(G6/DIN14) U12.7(3B3)
UB921_DIN15: U8.42(G7/DIN15) U12.10(4B3)
UB921_DIN16: U8.25(DIN0/R0/GPIO0) U12.12(5B3)
UB921_DIN17: U8.26(DIN1/R1/GPIO1) U12.14(6B3)
UB921_DIN18: U8.27(DIN2/R2) U12.16(7B3)
UB921_DIN19: U8.28(DIN3/R3) U12.20(8B3)
UB921_DIN20: U8.29(DIN4/R4) U12.22(9B3)
UB921_DIN21: U8.32(DIN5/R5) U12.24(10B3)
UB921_DIN22: U8.33(DIN6/R6) U12.26(11B3)
UB921_DIN23: U8.34(DIN7/R7) U12.28(12B3)
UB921_FSEL: R30.1 R336.1 U8.15(FSEL)
UB921_IDX: R20.2 R24.1 U8.6(IDX)
UB921_INTB: R66.2 TP122.1(TP) U43.15(P15)
UB921_INTB_R: R64.2 R65.1 R66.1 U8.31(INTB)
UB921_MODE_SEL: R62.2 R70.1 U8.24(MODE_SEL)
UB921_REM_INTB: TP31.1(TP) U8.16(REM_INTB)
UB921_RESETN: R55.2 TP120.1(TP) U8.21(PDB) U43.13(P13)
UB926_CMLOUTN: TP21.1(TP) U2.53(CMLOUTN)
UB926_CMLOUTP: TP23.1(TP) U2.52(CMLOUTP)
UB926_DE: TP29.1(TP) U2.6(DE)
UB926_GPIO1: J1.30 R535.1
UB926_GPIO2: J1.75 U2.28(ROUT8/G0/GPIO2)
UB926_GPIO3: J1.79 U2.27(ROUT9/G1/GPIO3)
UB926_GPIO_SPARE: R534.1 TP108.1(TP) U15.7(P06)
UB926_HS: TP28.1(TP) U2.8(HS)
UB926_I2S_CLK: R18.1 U17.6(2B2)
UB926_I2S_DA: U2.45(I2S_DA/GPO_REG6) U17.3(1B2)
UB926_I2S_DB: U2.18(ROUT17/B1/GPO_REG5/I2S_DB) U17.13(4B2)
UB926_I2S_WC: U2.30(I2S_WC/GPO_REG7) U17.10(3B2)
UB926_IDX: R13.2 R14.1 U2.56(IDX)
UB926_INTN: R15.1 U2.16(BISTC/INTB_IN)
UB926_LOCK: TP109.1(TP) U2.32(LOCK) U15.8(P07)
UB926_MCLK: TP27.1(TP) U2.60(MCLK)
UB926_PASS: TP19.1(TP) U2.42(PASS)
UB926_PCLK: R19.2 U2.5(PCLK)
UB926_RESETN: R329.1 TP105.1(TP) U2.59(PDB) U15.4(P03)
UB926_ROUT13: TP22.1(TP) U2.22(ROUT13/G5)
UB926_TUNER_RESET: R4.2 TP107.1(TP) U2.41(ROUT0/R0/GPIO0) U15.6(P05)
UB926_VS: TP30.1(TP) U2.7(VS)
V_DVDD: C33.1 C34.1 C243.1 C256.1 FL22.1 R59.1 R346.2 U41.1(DVDD1) U41.12(DVDD2) U41.33(DVDD3)
V_PVDD: C235.1 C237.1 C238.1 FL20.1 U41.18(PVDD)
V_TVDD: C30.1 C31.1 C242.1 FL21.1 R21.1 U41.23(TVDD1) U41.29(TVDD2)
VCOMAD1: C139.1 C145.1 C152.1 C159.1 C330.1 C341.1 C349.1 C356.1 C771.1 C772.1 C773.1 C774.1 R230.1 R239.1 R465.1 R472.1 U26.3(+INA) U26.5(+INB) U27.3(+INA) U27.5(+INB) U28.3(+INA) U28.5(+INB) U29.3(+INA) U29.5(+INB) U51.3(+INA) U51.5(+INB) U53.3(+INA) U53.5(+INB) U54.3(+INA) U54.5(+INB) U55.3(+INA) U55.5(+INB) U179.1(OUTA) U179.2(-INA)
VCOMAD1_CODEC: C171.1 U32.1(VCOMAD) U179.3(+INA) U179.5(+INB)
VCOMAD1_SPARE: TP171.1(TP) U179.6(-INB) U179.7(OUTB)
VCOMAD2: C103.1 C113.1 C119.1 C124.1 C309.1 C317.1 C324.1 C336.1 C767.1 C768.1 C769.1 C770.1 R182.1 R192.1 R425.1 R432.1 U20.3(+INA) U20.5(+INB) U22.3(+INA) U22.5(+INB) U23.3(+INA) U23.5(+INB) U24.3(+INA) U24.5(+INB) U48.3(+INA) U48.5(+INB) U49.3(+INA) U49.5(+INB) U50.3(+INA) U50.5(+INB) U52.3(+INA) U52.5(+INB) U180.1(OUTA) U180.2(-INA)
VCOMAD2_CODEC: C100.1 U19.1(VCOMAD) U180.3(+INA) U180.5(+INB)
VCOMAD2_SPARE: TP172.1(TP) U180.6(-INB) U180.7(OUTB)
VCOMDA1: C193.1 U32.15(VCOMDA)
VCOMDA2: C74.1 U19.15(VCOMDA)
VLDO_CAM_1V8: R2.1 U1.5(OUT2)
VLDO_CAM_3V3: R3.1 U1.6(OUT1)
VOUT0_DATA0: J1.39 U11.2(1A)
VOUT0_DATA1: J1.43 U11.4(2A)
VOUT0_DATA2: J1.41 U11.6(3A)
VOUT0_DATA3: J1.45 U11.9(4A)
VOUT0_DATA4: J1.47 U11.11(5A)
VOUT0_DATA5: J1.23 U11.13(6A)
VOUT0_DATA6: J1.49 U11.15(7A)
VOUT0_DATA7: J1.25 U11.18(8A)
VOUT0_DATA8: J1.27 U11.21(9A)
VOUT0_DATA9: J1.29 U11.23(10A)
VOUT0_DATA10: J1.31 U11.25(11A)
VOUT0_DATA11: J1.14 U11.27(12A)
VOUT0_DATA12: J1.18 U12.2(1A)
VOUT0_DATA13: J1.16 U12.4(2A)
VOUT0_DATA14: J1.10 U12.6(3A)
VOUT0_DATA15: J1.8 U12.9(4A)
VOUT0_DATA16: J1.42 U12.11(5A)
VOUT0_DATA17: J1.50 U12.13(6A)
VOUT0_DATA18: J1.46 U12.15(7A)
VOUT0_DATA19: J1.40 U12.18(8A)
VOUT0_DATA20: J1.44 U12.21(9A)
VOUT0_DATA21: J1.48 U12.23(10A)
VOUT0_DATA22: J1.28 U12.25(11A)
VOUT0_DATA23: J1.32 U12.27(12A)
VOUT0_DE: J1.34 U10.6(3A)
VOUT0_EXTPCLKIN: J1.21 U10.2(1A)
VOUT0_HSYNC: J1.12 U10.4(2A)
VOUT0_PCLK: J1.36 U10.27(12A)
VOUT0_VSYNC: J1.33 U10.9(4A)
VOUTEXP_INTB: J2.17 R354.2 TP124.1(TP) U43.22(I\N\T\)
VOUTEXP_P04: TP34.1(TP) U43.6(P05)
VOUTEXP_P05: TP33.1(TP) U43.7(P06)
VOUTEXP_P16: TP38.1(TP) U43.16(P16)
VOUTEXP_P17: TP39.1(TP) U43.17(P17)
VPFE0_DATA0: R37.1 U12.44(5B2)
VPFE0_DATA1: R38.1 U12.42(6B2)
VPFE0_DATA2: R33.1 U12.40(7B2)
VPFE0_DATA3: R34.1 U12.37(8B2)
VPFE0_DATA4: R39.1 U12.35(9B2)
VPFE0_DATA5: R40.1 U12.33(10B2)
VPFE0_DATA6: R35.1 U10.42(6B2)
VPFE0_DATA7: R36.1 U10.40(7B2)
VPFE0_DATA8: R45.1 U12.51(2B2)
VPFE0_DATA9: R46.1 U12.46(4B2)
VPFE0_DATA10: R41.1 U10.48(3B2)
VPFE0_DATA11: R42.1 U10.37(8B2)
VPFE0_DATA12: R532.1 U10.35(9B2)
VPFE0_DATA13: R533.1 U11.44(5B2)
VPFE0_HD: R43.1 U11.53(1B2)
VPFE0_PCLK: R31.1 U10.53(1B2)
VPFE0_VD: R44.1 U11.48(3B2)
VREF2_CAM: C219.1 R325.2 U36.7(VREF2) U36.8(EN)
VSYS_IO_3V3: J2.100 J2.102 J2.104 TP8.1(TP)
WKUP_I2C0_SCL: J1.65 R218.1 R393.1 U30.6(SCL)
WKUP_I2C0_SDA: J1.63 R216.1 R394.1 U30.5(SDA)
N19811491: C42.2 U8.23(CMF)
N19811520: R47.2 U8.18(RES1)
N19811540: C32.1 U8.14(CAPP12)
N19811568: C35.1 U8.17(CAPHS12)
N19811570: C28.1 C29.1 U8.7(CAPL12)
N23276319: R338.1 U41.11(MSEN/PO1)
N23670479: C204.1 R304.2
N23670482: C196.1 R290.2
N23684707: C278.1 R101.2
N23911217: J17.31 R233.1
N23911219: J17.29 R235.1
N23981776: C147.2 R226.2 R227.2
N23985739: C158.2 R244.2 R245.2
N23990208: R243.2 R244.1 R247.2
N23990244: R223.2 R225.2 R226.1
N24479449: C342.2 R460.2 R461.2
N24479767: R458.2 R461.1 R462.2
N24480253: R479.1 R480.2 R481.2
N24480259: C354.2 R478.2 R479.2
N24488350: C373.1 R514.2
N24488546: C380.1 R526.2
N24492127: C183.1 R280.2
N24492135: C359.1 R488.2
N24492520: C168.1 R255.2
N24492543: C366.1 R504.2
N24497380: C118.2 R196.2 R197.2
N24497698: R195.2 R196.1 R199.2
N24498184: R175.2 R176.2 R177.1
N24498190: C105.2 R177.2 R178.2
N24501627: C310.2 R419.2 R420.2
N24501939: R418.2 R420.1 R421.2
N24502423: R437.1 R438.2 R440.2
N24502429: C322.2 R436.2 R437.2
N24516386: C89.1 R165.2
N24516394: C293.1 R398.2
N24516779: C72.1 R143.2
N24516802: C301.1 R412.2
N24517434: C64.1 R133.2
N24517442: C279.1 R372.2
N24517839: C52.1 R109.2
N24517862: C286.1 R386.2
N24561941: R50.1 U9.6(SCL2)
N24561944: R51.1 U9.5(SDA2)
N24562809: C38.1 R56.2 U9.7(VREF2) U9.8(EN)
N24589481: R5.2 R534.2 R535.2 U2.40(ROUT1/R1/GPIO1)
N24613389: R110.2 U15.18(ADDR)
N24636980: R315.1 U35.6(1Y)
N24637007: R323.1 U35.3(2Y)
N24638437: R326.2 U38.1(STANDBY)
N24673543: TP44.1(TP) U11.37(8B2)
N24673545: TP45.1(TP) U11.40(7B2)
N24673547: TP46.1(TP) U11.51(2B2)
N24676160: TP41.1(TP) U10.3(1B3)
N24676162: TP32.1(TP) U10.54(1B1)
N24733661: R314.1 U35.7(\\2\\\O\\\E)
N24733666: R321.1 U35.1(\\1\\\O\\E)
N24736802: R120.2 U14.2(DIR)
N24788879: C217.1 R327.1 U37.7(VREF2)
N24793440: R213.1 U25.1(\\1\\\O\\E) U25.7(\\2\\\O\\\E)
N24805264: R347.2 U43.18(ADDR)
N24817584: R183.1 U21.1(\\1\\\O\\E) U21.7(\\2\\\O\\\E)
N24985508: R99.1 R100.1 U13.3(A) U13.6(Y)
N24986462: C51.2 R104.1
N24987908: LD2.2 R358.2
N24987961: LD2.1 Q2.3(DRAIN)
N24990777: LD3.2 R367.2
N24990859: LD3.1 Q3.3(DRAIN)
N24990930: LD1.2 R350.2
N24990935: LD1.1 Q1.3(DRAIN)

Pads without a net: J1 35 62 66 97 98 99 104 106 116 117; J2 11 12 13 14 18 24 26 27 29 31 33 35 36 37 38 46 50 54 56 58 60 62 64 65 66 69 70 71 72 73 74 75 76 83 84 85 86 87 88 89 90 91 92 93 94 95 96 97 98 99 101 103 106 108 110 111 112 113 115 117; J3 9 11 27 28 29 30; J4 14 17; J10 7; J14 1 3 5 6 7 8 9 13 14 15 16 17 18 21 22 23 24 25 26 27 28 31 32 36 37 38; J17 1 2 3 4 5 6 7 8 9 10 11 12 13 14 15 16 17 18 19 20 21 25 32 34 36 40 41 42 43 44 45 46 47 48 55 56 61 62 63 64 65 66 67 68 69 70 71 72 73 74 75 79 80 81 82 83 84 85 86 87 88 89 90 91 92 93 94 95 96 97 98 99 100 101 106 107 108 109 110 111 112 113 114 117 118 119 120; J20 1 2 3 4 5 6 7 8 9 10 11 12 14 15 16 17 18 23 24 25 26 27 28 29 30 31 32 33 34 35 36 37 38 39 40; MOD1 4 5; U2 9 10 11 12 14 17 19 20 21; U3 4 7; U5 10; U7 19 20; U8 11 12 13; U10 12 14 16 20 22 24 26 29 36 39 41 43 46 51; U11 33 35 42 46; U12 29 31 48 53; U14 5 8; U34 2 3 8 9; U39 1; U40 1 4 11 14; U41 49; U42 8 9 14; U43 1 2 3 4 5 8; U44 1 4 11 14

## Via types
v1: diameter 0.457, hole 0.203, TOP to BOTTOM, 1815 vias

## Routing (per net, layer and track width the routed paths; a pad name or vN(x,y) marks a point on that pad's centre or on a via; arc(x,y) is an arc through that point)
DGND: length 781.7
  TOP w0.203: J1.126 89.14,119.51 J1.82 ; J2.1 84.01,45.13 v1(83.36,44.48) ; U6.39 v1(55.74,172.69) ; v1(94.77,103.64) 94.59,103.46 91.35,103.46 J1.38 ; v1(94.39,66.94) 94.26,67.06 92.94,67.06 92.51,66.63 J2.68 ; U7.10 67.05,168.98 66.8,169.22 v1(66.8,169.27) ; J1.5 85.09,95.46 83.44,95.46 v1(83.21,95.23) 83.21,95.21 83.41,95.01 J1.3 ; J1.108 92.24,126.01 92.48,125.76 v1(93.09,125.76) ; U3.2 U3.3 v1(39.69,174.95) ; U7.28 v1(71.45,172.69) ; v1(81.23,68.23) 83.24,68.23 84.14,69.13 J2.77 ; v1(44.9,174.95) U4.2 U4.3 ; v1(87.1,120.51) 86.1,119.51 J1.81 ; U6.10 55.74,169.08 v1(56.14,169.48) ; J1.52 93.18,107.01 94.54,108.36 v1(94.54,108.92) ; J2.40 89.64,54.63 89.13,54.13 v1(89.13,52.53) ; J1.1 v1(82.94,94.51) ; v1(79.31,142.86) 79.78,142.39 U11.19 ; J1.96 89.6,123.01 89.43,123.17 v1(89.43,124.95) ; v1(41.17,166.99) 42.3,166.99 42.5,167.19 U4.9 ; J1.95 86.32,123.01 86.8,123.49 v1(86.8,124.7) ; U3.8 v1(37.69,174.95) ; v1(82.78,98.53) 83.21,98.97 85.1,98.97 J1.19 ; J2.67 84.18,66.63 83.41,67.39 v1(81.28,67.39) ; v1(88.14,108.09) 87.06,107.01 J1.51 ; v1(52.93,170.47) 53.34,170.06 U6.4 ; U1.4 61.55,195.21 ; v1(94.36,142.16) 94.63,142.16 95.22,141.57 U12.19 ; v1(22.04,180.23) 21.54,179.73 U2.54 ; v1(48.41,99.55) 49.09,100.23 U19.50 ; v1(74.53,142.48) 74.28,142.22 U11.8 ; J2.123 87.29,54.63 J2.39 ; v1(63.87,150.61) 64.21,150.27 U10.38 ; v1(90.6,81.85) 91.3,81.15 J2.120 ; U6.21 v1(60.14,169.15) ; U7.4 v1(64.65,169.15) ; U4.8 42.5,174.85 v1(42.4,174.95) ; v1(38.1,170.24) 37.54,169.68 37.54,169.22 37.64,169.12 37.64,168.07 U3.9 ; U2.43 22.08,182.81 v1(22.04,182.77) 21.58,183.23 U2.47 ; J1.120 89.78,129.01 v1(89.51,128.74) ; J2.119 83.95,79.63 v1(83.57,80.02) ; U7.45 v1(64.65,172.69) ; U15.9 58.76,131.13 v1(59.01,130.88) ; U6.28 v1(60.14,172.69) ; U11.38 v1(79.78,149.41) ; 87.38,118.63 87.38,116.7 86.69,116.01 J1.67 ; U12.49 v1(89.72,146.1) ; v1(79.81,71.08) 82.98,71.08 83.93,70.13 J2.81 J2.79 ; J1.37 v1(86.7,103.51) ; U19.2 57.17,103.89 ; J2.105 84.25,76.13 v1(83.74,75.62) ; v1(82.42,44.81) 83.24,45.63 J2.3 ; v1(89.48,114.13) 89.48,115.6 89.89,116.01 J1.68 ; U10.19 64.19,140.71 v1(64.19,141.82) ; v1(89.92,143.75) 89.92,141.97 89.72,141.77 U12.8 ; U7.39 v1(67.05,172.69) ; U7.15 v1(69.05,169.15) ; v1(74.57,146.77) 74.48,146.87 74.48,147.02 74.28,147.23 U11.49 ; v1(71.12,169.27) 71.24,169.27 71.45,169.07 U7.21 ; U5.9 v1(47.32,166.89) ; U6.45 v1(53.34,172.69) ; U7.34 v1(69.05,172.69) ; U6.34 v1(57.74,172.69) ; v1(47.22,174.99) 47.22,174.96 47.29,174.89 47.29,173.85 U5.8 ; J1.107 86.22,126.01 v1(86.66,125.56) ; U6.15 v1(57.74,169.15) ; J1.119 v1(85.14,129.85) ; v1(95.22,149.41) U12.38 ; v1(95.02,100.82) 95.02,100.44 93.55,98.97 91.34,98.97 J1.20 ; v1(81.86,46.62) 82.35,46.13 J2.5
  TOP w0.254: v1(55.52,143.29) 58.17,143.29 58.71,142.74 U10.8 ; v1(49.8,104.6) 49.09,103.89 U19.47 ; v1(54.88,104.6) 56.46,104.6 57.17,103.89 ; U32.50 55.59,55.08 v1(56.35,55.84) ; U10.49 58.71,147.33 60.19,145.86 v1(61.49,145.86) ; U32.16 v1(46.64,40.33) ; v1(54.88,108.41) 54.9,108.39 U19.11 ; U19.16 v1(58.04,112.03) ; v1(49.8,43.41) 49.78,43.43 U32.11 ; U32.47 55.59,47.93 v1(54.88,47.22) ; U32.2 45.69,47.93 45.44,48.19 v1(45.44,48.92) ; U19.33 v1(46.64,112.03) ; U32.33 58.04,40.7
  TOP w0.305: 41.81,134.48 41.83,134.45 C277.2
  TOP w0.381: R70.2 v1(28.44,154.12) ; v1(45.32,126.43) C61.2 v1(46.42,125.58) ; C23.2 v1(14.56,176.75) 13.78,176.75 R14.2 ; C180.2 v1(63.94,49.03) ; C182.2 v1(66.32,49.03) ; v1(94.59,42.55) 94.59,43.09 95.22,43.72 C176.2 96.6,43.72 96.98,43.34 v1(96.98,42.58) ; R296.2 v1(13.59,27.51) ; v1(28.4,188.92) 28.4,187.54 C9.2 ; v1(48.7,183.5) C15.2 v1(46.48,182.84) ; R273.2 v1(23.53,39.6) ; v1(65.46,195.93) C2.2 v1(64.47,196.59) ; C312.2 v1(51.76,91.42) ; C97.2 v1(65.41,100.24) ; C195.2 v1(64.02,35.69) ; C103.2 v1(36.46,94.53) ; v1(31.17,152.1) 30.63,152.64 C44.2 ; R48.2 79.22,162.21 79.46,161.97 79.46,161.44 79.22,161.2 R52.2 79.22,160.31 v1(79.5,160.03) ; v1(88.52,166.93) 89.04,167.45 C30.2 ; R266.2 v1(13.39,43.76) ; J1.121 v1(88.92,93.32) ; v1(52.58,147.73) 47.6,147.73 46.74,146.87 46.74,142.48 v1(46.55,142.29) ; C49.2 v1(45.05,133.88) ; J2.128 v1(88.22,82.48) ; v1(28.5,153.27) 29.22,153.99 C43.2 ; C128.2 94.17,76.86 v1(94.39,76.64) ; U17.8 65.28,121.33 v1(64.77,121.84) ; C34.2 85.5,164.87 v1(85.98,164.39) ; R289.2 v1(23.47,31.72) ; C162.2 v1(68.28,49.1) ; U23.4 v1(35.75,82.86) ; C58.2 v1(16.03,125.74) ; C165.2 v1(56.35,54.82) ; R301.2 v1(24.91,23.09) ; C40.2 v1(20.49,159.43) ; C210.2 v1(18.19,197.77) ; C220.2 90.85,181.03 91.06,181.24 91.06,182.84 v1(90.85,183.05) ; C32.2 v1(22.09,166.97) ; C83.2 v1(60.85,112.53) ; U14.16 v1(53.36,134.98) ; 58.04,40.7 v1(58.04,40.33) ; C99.2 v1(30.56,98.57) ; C6.2 87.37,190.41 86.99,190.03 v1(86.08,190.03) ; U31.4 21.07,40.36 v1(21.08,40.37) ; R96.1 R97.1 42.68,144.01 v1(42.42,143.75) ; C38.2 41.86,158.71 v1(41.86,157.56) ; C110.2 95.94,91.88 v1(95.81,91.75) ; C62.2 v1(40.16,125.62) ; v1(60.85,113.55) 62.03,112.37 C84.2 ; v1(18.3,186.33) C12.2 v1(17.22,185.48) ; R47.1 v1(22.01,162.71) ; C161.2 v1(42.04,55.33) ; v1(21.11,24.01) 21.09,24.03 U33.4 ; v1(92.33,166.93) 92.04,167.22 C31.2 ; J1.125 v1(88.92,113.32) ; C5.2 v1(70.74,190.76) ; v1(86.8,124.7) 87.05,124.94 J1.127 ; C100.2 v1(60.52,99.3) ; v1(14.91,185.52) C14.2 v1(14,184.86) ; C203.2 v1(13.59,26.28) ; R263.1 v1(59.49,51.22) ; C166.2 v1(57.59,54.82) ; v1(28.12,106.28) 28.1,106.3 U18.4 ; C152.2 v1(26.24,57.45) ; C193.2 v1(42.06,38.83) ; C145.2 v1(36.46,63.9) ; C192.2 v1(58.94,39.02) ; v1(21.26,122.03) 21.25,122.04 U16.4 ; C45.2 v1(26.52,142.45) ; C167.2 v1(62.35,54.01) ; U27.4 v1(35.75,60.54) ; U20.4 v1(35.75,93.47) ; v1(51.97,181.21) 52.92,182.16 R10.1 ; R59.2 81.88,156.93 v1(81.9,156.91) ; C174.2 v1(97.6,43.68) ; C190.2 v1(42.56,40.33) ; J2.122 v1(88.22,51.94) ; R297.2 v1(60.93,23.53) ; J1.128 v1(87.52,130.21) ; v1(22.1,171.43) 22.99,172.32 C25.2 ; C127.2 v1(95.68,77.35) ; R174.1 v1(42.98,102.2) ; R328.2 v1(94.75,181.55) ; C107.2 v1(18.76,93.78) ; C86.2 v1(69.83,106.31) ; R300.2 v1(13.59,25.1) ; C102.2 v1(47.16,98.33) ; C194.2 v1(58.13,37.33) ; R58.2 90.04,159.06 v1(89.79,159.31) ; J2.121 v1(88.22,42.29) ; J1.122 v1(88.92,98.59) ; C119.2 v1(36.46,83.93) ; v1(9.91,133.84) 10.52,133.84 C50.2 10.57,132.7 v1(9.91,132.7) ; v1(42.48,41.26) 42.86,41.64 C188.2 ; v1(79.83,167.57) 79.83,166.91 79.48,166.56 R28.2 ; v1(54.22,76.07) C131.2 v1(53.04,76.92) ; C42.1 v1(25.4,155.43) ; C8.2 v1(29.13,174.48) ; C1.2 v1(55.07,196.46) ; R272.1 v1(63.94,46.49) ; U29.4 v1(35.75,49.94) ; C20.2 v1(30.94,178.24) ; R108.2 v1(23.6,129.74) ; J2.123 v1(88.22,58.29) J2.124 ; C175.2 v1(16.03,44.06) ; v1(38.67,126.43) C60.2 v1(37.58,125.58) ; R142.2 v1(30.52,114) ; R120.1 v1(47.52,123.57) ; R112.2 v1(74.47,127.69) ; R53.2 R49.2 75.98,161.72 v1(75.69,161.43) ; v1(18.88,155.1) C39.2 18.88,157.94 v1(18.87,157.95) ; R278.1 v1(63.91,42.04) ; C149.2 v1(18.76,60.85) ; U14.12 v1(55.92,128.08) ; C26.2 20.02,173.68 v1(20.02,173.67) ; v1(69.72,114.26) 69.41,114.57 U17.15 ; J2.127 v1(88.22,78.29) ; v1(42.57,155.53) 42.93,155.89 U9.1 ; R130.1 72.18,122.32 v1(72.34,122.49) ; C164.2 v1(58.96,54.82) ; C10.2 v1(69.7,187.88) ; v1(26.39,136.3) 26.2,136.49 U13.2 ; C24.2 v1(14.53,174.97) ; C21.2 v1(14.56,178.81) ; J2.126 v1(88.22,72.45) ; v1(58.12,196.51) R1.1 v1(58.99,195.85) ; C178.2 v1(43.25,49.58) ; C181.2 v1(61.39,48.41) ; C18.2 v1(15.61,180.24) ; C27.2 v1(30.63,171.86) ; C95.2 v1(62.38,100.68) ; C35.2 v1(21.19,164.17) ; C46.2 v1(7.38,136.1) ; R166.1 v1(41.58,104.25) ; J1.123 v1(88.92,104.94) ; v1(12.47,152.64) 12.47,152.63 R71.2 ; R5.1 v1(24.08,188.92) ; U14.11 v1(54.66,126.97) ; v1(45.43,76.07) C130.2 v1(46.6,76.92) ; C211.2 v1(16.81,197.77) ; C116.2 v1(30.56,87.96) ; C191.2 v1(58.94,40.33) ; C201.2 v1(16.03,27.73) ; C70.2 v1(72.37,116.65) ; C87.2 v1(66.27,106.31) ; 93.92,90.9 93.22,90.2 v1(93.22,89.57) ; C336.2 v1(25.51,71.21) ; C33.2 93.66,166.87 v1(93.6,166.93) ; R151.2 v1(13.26,108.88) ; 32.01,70.35 C328.2 32.98,70.35 v1(33.45,70.82) ; C48.2 v1(45.06,135.11) ; U14.22 v1(49.46,134.98) ; C74.2 v1(59.77,115.52) ; U30.4 v1(78.14,52.91) ; C138.2 v1(95.47,72.44) ; C144.2 v1(30.56,65.64) ; C101.2 v1(45.92,98.33) ; v1(68.34,189.4) C3.2 v1(67.25,190.32) ; C93.2 v1(60.89,101.49) ; v1(87.32,118.68) 87.42,118.59 J1.126 ; C159.2 v1(36.46,53.29) ; U52.4 v1(15.32,77.15) ; v1(45.67,143.26) 45.41,143.52 R98.1 ; R23.2 v1(29.01,168.19) ; J2.125 v1(88.22,65.59) ; C132.2 v1(48.03,76.24) ; C29.2 v1(32.14,171.05) ; U22.4 v1(23.97,88.17) ; C79.2 v1(43.56,112.53) ; R254.2 v1(23.6,48.06) ; R116.1 v1(74.47,126.73) ; R99.2 v1(25.27,142.46) ; R25.2 v1(77.32,166.2) ; R156.2 v1(32.75,105.23) ; C28.2 v1(30.4,171.05) ; R128.2 v1(13.34,123.19) ; R129.2 v1(26.11,120.54) ; J1.124 v1(88.92,110.21) ; C179.2 v1(44.5,49.58) ; U24.4 v1(27.22,74.75) ; C334.2 v1(20.39,72.05) ; C133.2 v1(51.48,76.24) ; C82.2 v1(63.53,113.55) ; R155.2 v1(13.26,106.62) ; 61.55,195.21 v1(61.55,195.98) ; R4.1 v1(22.8,188.92) ; C85.2 v1(21.08,105.73) ; C94.2 v1(59.71,101.48) ; C113.2 v1(26.24,90.37) ; C157.2 v1(42.04,57.01) ; C7.2 v1(70.25,189.33) ; v1(63.35,190.36) C4.2 v1(65.86,190.36) ; C63.2 v1(43.71,125.62) ; C155.2 v1(30.56,55.04) ; C77.2 v1(65.79,113.28) ; R158.1 v1(41.58,108.72) ; C171.2 v1(45.02,53.7) ; R269.2 v1(13.34,41.51) ; R24.2 v1(35.23,168.35) ; U14.19 v1(51.41,134.98) ; C311.2 v1(53.51,91.42) ; R55.1 v1(22.51,159.32) ; C13.2 v1(31.44,185.56) ; C41.2 v1(23.89,155.37) ; C124.2 v1(13.63,74.25) ; C137.2 v1(93.85,73.33) ; U14.13 v1(55.31,132.44) ; R118.2 v1(13.34,125.44) ; C80.2 v1(44.72,112.53) ; C212.2 v1(14.17,197.54) ; C54.2 v1(45.71,127.38) ; U28.4 v1(23.97,55.25)
  TOP w0.508: C22.2 v1(75.38,176.77) ; C19.2 v1(75.82,180.38)
  BOTTOM w0.203: U35.4 v1(36.25,182.35) ; U21.4 65.91,95.11 v1(66.23,94.79) ; v1(93.6,165.66) 94.31,166.37 U41.34 ; v1(64.83,72.25) 64.33,71.74 U25.4 ; v1(93.6,166.93) 93.54,166.99 U41.32 ; U41.16 85.92,166.87 v1(85.98,166.93) 86.04,166.99 U41.17 ; U41.26 90.54,167.45 v1(91.06,166.93) ; U41.20 87.54,167.22 v1(87.25,166.93) ; v1(66.62,159.39) 66.75,159.27 U43.9 ; v1(85.98,159.31) 86.04,159.25 U41.64 ; U41.48 93.66,159.37 v1(93.6,159.31)
  BOTTOM w0.254: J4.5 v1(94.85,189.71) ; J4.2 v1(96.35,189.71) ; J4.8 v1(93.35,189.71) ; J4.11 v1(91.85,189.71)
  BOTTOM w0.305: U180.4 59.26,95.8 59.57,96.1 v1(59.57,96.51)
  BOTTOM w0.381: C226.2 66.83,172.91 v1(67.05,172.69) ; J14.2 v1(56.13,79.07) ; v1(79.31,142.86) 78.78,142.32 C274.2 ; U45.23 46.1,143.84 46.55,143.4 v1(46.55,142.29) 47.31,141.52 47.31,135.94 46.61,135.24 46.61,133.46 46.22,133.08 C277.2 37.97,133.08 37.36,132.47 C278.2 ; C314.2 v1(30.56,92.78) ; J17.123 v1(89.13,72.53) ; C232.2 v1(45.3,172.18) ; C119.2 v1(36.46,83.93) ; v1(71.12,169.27) 71.12,168.13 C247.2 ; C270.2 v1(41.04,142.85) ; C246.1 41.19,169 v1(41.2,168.99) ; v1(69.22,185.1) 69.19,185.1 69.07,184.98 J6.6 ; v1(23.34,107) 23.16,106.82 C299.2 ; U45.6 48.85,143.84 v1(48.49,144.2) ; J17.27 95.48,70.17 v1(96.42,71.1) ; C241.2 66.28,171.22 v1(67.18,170.32) ; v1(54.69,137.27) 54.69,137.27 C276.2 ; J17.121 v1(89.13,82.82) ; v1(14.08,165.87) D4.2 v1(18.66,165.87) ; R142.2 v1(30.52,114) ; U54.4 v1(23.97,59.65) ; J6.SH4 v1(53.07,185.11) ; v1(60.14,169.15) 59.92,168.93 C249.2 ; 52.85,62.05 53.08,61.82 ; J14.40 v1(71.33,79.07) ; C113.2 v1(26.24,90.37) ; J17.26 v1(83.83,70.97) ; FL13.1 v1(100.15,188.09) ; FL13.1 v1(98.55,188.09) ; FL13.1 v1(99.35,187.31) ; C215.2 v1(43.74,182.6) ; v1(28.93,170.39) 28.02,171.3 28.02,172.48 v1(29.06,173.52) ; v1(48.31,104.6) 48.1,104.39 C303.2 ; U34.19 v1(94.1,187.35) ; v1(23.17,154.32) C260.2 v1(22.43,155.1) ; C272.2 v1(38.6,142.89) ; v1(37.47,147.05) 37.47,147.56 38.3,148.39 Q2.2 ; v1(94.23,43.7) 94.23,45.86 93.92,46.17 J17.77 ; R289.2 v1(23.47,31.72) ; C269.2 52.32,147.48 v1(52.58,147.73) 53.01,147.3 C268.2 ; U49.4 v1(23.97,92.57) ; R176.1 24,94.84 ; U56.4 20.29,46.06 v1(20.63,46.4) ; C285.2 v1(16.03,122.74) ; J17.125 v1(89.13,58.88) J17.126 ; v1(23.62,171.31) 23.45,171.13 C240.2 ; R335.2 v1(99.19,166) ; C159.2 v1(36.46,53.29) ; R300.2 v1(13.59,25.1) ; U47.4 27.34,111.83 v1(27.48,111.97) ; R365.1 53.86,135.48 v1(53.36,134.98) ; U55.4 v1(35.75,54.35) ; R331.2 v1(13.61,167.94) ; v1(59.74,171.97) 60.11,171.6 U39.3 ; C234.2 v1(78.28,174.54) ; U46.4 20.29,127.74 v1(20.63,128.08) ; Q3.2 v1(35,138.04) ; v1(44.32,178.42) 44.51,178.23 C219.2 ; v1(2.38,170.96) D3.2 v1(2.38,175.94) ; R314.2 38.42,186.99 v1(38.43,186.98) ; U42.5 40.47,161.23 v1(40.56,161.32) 40.56,161.8 40.15,162.22 ; 24.05,52.39 24.05,53.05 ; C273.2 v1(36.76,142.89) ; U53.4 v1(35.75,64.96) ; C248.1 66.83,169.2 66.8,169.22 v1(66.8,169.27) ; J20.42 v1(57.82,22.49) ; C139.2 v1(25.51,71.21) ; v1(73.91,180.89) 73.63,181.18 J6.SH1 ; U42.10 40.47,155.36 v1(40.69,155.58) ; J14.30 v1(67.33,79.07) ; R361.2 v1(40.45,140.99) ; v1(37.08,161.4) 36.91,161.57 R342.2 ; v1(81.41,45.12) 82.46,46.17 J17.78 ; U57.4 v1(20.29,29.9) ; C217.2 v1(83.49,179.66) ; C275.2 94.6,141.92 v1(94.36,142.16) ; J14.29 v1(67.33,87.82) ; v1(13.26,108.88) R151.2 ; J6.25 59.61,181.13 v1(59.61,179.28) ; v1(51.41,134.98) 50.81,135.59 R366.1 ; 24.05,62.24 24.05,61.58 ; v1(51.64,148.78) 51.69,148.73 C267.2 ; R486.2 v1(81.1,48.24) ; v1(25.65,147.81) 25.65,148.69 24.89,149.46 ; U50.4 v1(35.75,87.28) ; U37.1 80.23,177.82 80.56,177.49 C222.2 v1(80.56,176.36) ; J17.115 v1(93.5,26.97) ; C252.2 v1(42.75,164.08) ; v1(56.14,169.48) 55.52,168.86 C250.1 ; C271.2 v1(34.32,142.85) ; C261.2 64.19,141.78 64.19,141.79 v1(64.19,141.82) ; J14.42 v1(57.82,83.45) ; R269.2 v1(13.34,41.51) ; U36.1 45.83,183.49 v1(46.48,182.84) ; U51.4 v1(18.88,77.15) ; C216.2 40.81,182.45 v1(40.82,182.46) ; C243.2 v1(76.92,168.58) ; U34.14 90.85,187.15 v1(90.93,187.23) ; R311.2 v1(42.48,188.53) ; J17.122 v1(89.13,78.88) ; v1(11.4,177.02) 11.4,176.69 C223.2 12.8,177.27 v1(12.8,177.66) ; J17.128 v1(89.13,46.69) ; J17.129 v1(89.13,39.26) ; C379.2 v1(16.03,24.72) ; R330.2 23.39,168.67 R332.2 23.38,168 23.22,167.83 v1(21.97,167.83) ; R156.2 v1(32.75,105.23) ; C238.2 v1(84.67,173.93) ; v1(13.26,106.62) R155.2 ; J17.132 v1(89.13,23.13) ; R301.2 v1(24.91,23.09) ; C245.1 45.97,169 v1(45.97,168.99) ; v1(71.45,172.69) 71.23,172.91 C225.2 ; C352.2 v1(18.76,54.04) ; J6.8 68.07,184.9 v1(67.56,185.4) 67.07,184.91 J6.10 ; U44.2 v1(13.01,150.03) ; C141.2 v1(25.51,69.62) ; C348.1 v1(98.13,58.31) ; R349.2 v1(23.55,150.99) ; v1(43.25,49.58) 42.31,49.58 41.45,48.72 U179.4 ; U34.6 94.1,179.05 v1(93.93,178.88) ; J14.4 v1(56.93,79.07) ; C242.2 v1(83.75,168.36) ; v1(16.9,169.21) 16.62,168.93 U40.2 ; D2.2 v1(86.71,188.31) ; v1(20.02,173.67) 20.02,173.68 C26.2 ; v1(51.97,181.21) 52,181.18 J6.SH3 ; C330.2 v1(19.65,76.32) ; C325.2 v1(30.56,82.18) ; J20.20 v1(63.33,18.11) ; R266.2 v1(13.39,43.76) ; C369.2 49.32,42.93 v1(49.8,43.41) ; J17.127 v1(89.13,52.53) ; C233.2 v1(40.49,172.18) ; R340.1 v1(76.4,163.12) ; C251.2 R337.2 v1(75.97,164.39) ; v1(90.83,188.98) 91.17,188.65 D1.2 ; C103.2 v1(36.46,94.53) ; C214.2 v1(39.73,183.56) ; R273.2 v1(23.53,39.6) ; C258.2 44.16,157.52 44.15,157.54 v1(44.15,157.57) ; U38.2 v1(36.99,178.23) ; v1(55.74,172.69) 55.52,172.91 C228.2 ; J6.26 v1(59.07,185.14) ; C126.2 v1(12.97,72.75) ; J20.19 v1(63.33,26.86) ; v1(69.8,142.48) 69.8,142.47 R362.1 ; v1(81.9,156.91) C256.2 ; R336.2 22.67,164.44 22.4,164.17 v1(21.19,164.17) ; C259.1 v1(17.09,154.8) ; R329.2 21.45,177.1 v1(22.04,177.69) ; R321.2 v1(39.71,182.42) ; C365.2 v1(16.16,41.06) ; J14.20 v1(63.33,79.07) ; C263.2 v1(63.87,151.88) ; J17.130 v1(89.13,33.42) ; J14.39 v1(71.33,87.82) ; C235.2 v1(83.24,174.74) ; C357.2 v1(30.56,49.25) ; R108.2 v1(23.6,129.74) ; v1(11.05,156.65) C257.2 v1(11.05,153.65) ; R254.2 v1(23.6,48.06) ; R213.2 v1(62.83,74.31) ; J17.124 v1(89.13,66.69) ; C109.2 v1(64.41,89.91) ; R353.2 v1(23.55,149.72) ; C265.2 C262.2 68.95,152.57 v1(68.81,152.71) ; C244.1 v1(50.82,169) ; v1(60.14,172.69) 59.92,172.91 C227.2 ; v1(74.3,183.62) 73.94,183.98 J6.SH2 ; v1(97.79,60.03) C346.2 95.07,61.17 95.48,61.58 v1(97.71,61.58) ; J14.43 v1(69.63,83.45) ; C224.2 v1(76.85,174.36) ; R118.2 v1(13.34,125.44) ; C230.1 v1(15.68,174.11) ; J17.116 v1(84.75,26.97) ; C266.2 v1(63.87,150.61) ; Q1.2 v1(49.36,150.67) ; R498.2 v1(47.9,46.93) ; C320.2 v1(18.76,86.97) ; J14.10 v1(59.33,79.07) ; U26.4 v1(30.75,74.75) ; C237.2 v1(85.94,173.93) ; C136.2 v1(62.83,65.4) ; R128.2 v1(13.34,123.19) ; C298.2 55.67,108.89 v1(54.88,109.68) ; C253.2 v1(40.15,164.08) ; R296.2 v1(13.59,27.51) ; J14.44 v1(73.56,83.45) ; J20.43 v1(69.63,22.49) ; U48.4 v1(35.75,97.88) ; R129.2 v1(26.11,120.54) ; R183.2 v1(64.41,98.82) ; C213.2 v1(98.7,184.35) ; J17.131 v1(89.13,27.07) ; R351.1 v1(44.23,151.2) ; C344.2 v1(30.56,59.86) ; C145.2 v1(36.46,63.9) ; J14.19 v1(63.33,87.82) ; C152.2 v1(26.24,57.45) ; C231.2 v1(50.12,172.18) ; R195.1 24,86.17 ; J20.41 v1(53.89,22.49) ; C236.2 v1(79.85,173.93) ; J20.44 v1(73.57,22.49) ; J14.41 v1(53.88,83.45)
  BOTTOM w0.508: C19.2 v1(75.82,180.38) ; C22.2 v1(75.38,176.77)
  vias: v1(1.42,18.91) v1(1.56,51.01) v1(1.56,34.59) v1(1.83,195.96) v1(1.84,137.63) v1(1.83,11.16) v1(1.88,145.09) v1(1.96,162.14) v1(1.96,132.32) v1(7.87,198.06) v1(8.94,10.65) v1(10.24,162.5) v1(10.27,182.42) v1(10.25,164.41) v1(10.76,184.41) v1(11.28,181.92) v1(11.62,164.38) v1(11.57,162.51) v1(12.09,183.68) v1(12.13,142.49) v1(12.55,181.11) v1(12.91,164.37) v1(13.07,162.5) v1(13.51,182.94) v1(14.06,146.96) v1(14.63,180.86) v1(14.67,116.23) v1(16.05,10.69) v1(16.43,153.36) v1(16.43,152.35) v1(16.43,151.33) v1(16.43,150.31) v1(16.43,149.3) v1(16.84,101.06) v1(16.9,172.26) v1(16.9,171.24) v1(16.9,170.23) v1(16.9,168.2) v1(17.21,142.49) v1(17.45,153.36) v1(17.45,152.35) v1(17.45,151.33) v1(17.45,150.31) v1(17.45,149.3) v1(17.7,105.69) v1(17.92,172.26) v1(17.92,171.24) v1(17.92,170.23) v1(17.92,169.21) v1(17.92,168.2) v1(18.47,153.36) v1(18.47,152.35) v1(18.47,151.33) v1(18.47,150.31) v1(18.47,149.3) v1(18.5,116.31) v1(18.94,172.26) v1(18.94,171.24) v1(18.94,170.23) v1(18.94,169.21) v1(18.94,168.2) v1(19.86,161.91) v1(19.96,160.03) v1(21.06,17.92) v1(22.04,181.5) v1(22.04,178.96) v1(23.31,182.77) v1(23.31,181.5) v1(23.31,180.23) v1(23.31,178.96) v1(23.31,177.69) v1(23.44,101.23) v1(24.13,116.43) v1(24.26,113.45) v1(24.58,182.77) v1(24.58,181.5) v1(24.58,180.23) v1(24.58,178.96) v1(24.58,177.69) v1(25.85,182.77) v1(25.85,181.5) v1(25.85,180.23) v1(25.85,178.96) v1(25.85,177.69) v1(26.19,129.79) v1(27.12,182.77) v1(27.12,181.5) v1(27.12,180.23) v1(27.12,178.96) v1(27.12,177.69) v1(27.93,10.64) v1(28.16,163.48) v1(28.16,162.47) v1(28.16,161.45) v1(28.16,160.43) v1(28.16,159.42) v1(29.18,163.48) v1(29.18,162.47) v1(29.18,161.45) v1(29.18,160.43) v1(29.18,159.42) v1(29.83,32.85) v1(30.09,41.49) v1(30.19,163.48) v1(30.19,162.47) v1(30.19,161.45) v1(30.19,160.43) v1(30.19,159.42) v1(30.18,24.68) v1(30.73,129.82) v1(31.21,163.48) v1(31.21,162.47) v1(31.21,161.45) v1(31.21,160.43) v1(31.21,159.42) v1(32.23,163.48) v1(32.23,162.47) v1(32.23,161.45) v1(32.23,160.43) v1(32.23,159.42) v1(32.7,114) v1(33.66,179.21) v1(36.17,23.2) v1(36.68,197.89) v1(36.86,157.54) v1(37.06,10.59) v1(37.19,107.4) v1(37.81,115.04) v1(38.79,90.13) v1(39.45,58) v1(42.37,190.08) v1(45.72,140.06) v1(47.04,153.12) v1(48.64,197.99) v1(49.34,83.26) v1(49.42,10.65) v1(49.8,109.68) v1(49.8,108.41) v1(49.8,107.14) v1(49.8,105.87) v1(49.8,47.22) v1(49.8,45.95) v1(49.8,44.68) v1(49.8,42.14) v1(50.39,175.09) v1(50.67,164.37) v1(51.07,109.68) v1(51.07,108.41) v1(51.07,107.14) v1(51.07,105.87) v1(51.07,104.6) v1(51.07,47.22) v1(51.07,45.95) v1(51.07,44.68) v1(51.07,43.41) v1(51.07,42.14) v1(52.32,187.49) v1(52.34,109.68) v1(52.34,108.41) v1(52.34,107.14) v1(52.34,105.87) v1(52.34,104.6) v1(52.34,47.22) v1(52.34,45.95) v1(52.34,44.68) v1(52.34,43.41) v1(52.34,42.14) v1(53.61,109.68) v1(53.61,108.41) v1(53.61,107.14) v1(53.61,105.87) v1(53.61,104.6) v1(53.61,47.22) v1(53.61,45.95) v1(53.61,44.68) v1(53.61,43.41) v1(53.61,42.14) v1(54.88,107.14) v1(54.88,105.87) v1(54.88,45.95) v1(54.88,44.68) v1(54.88,43.41) v1(54.88,42.14) v1(55.93,120.66) v1(59.01,131.9) v1(59.01,129.87) v1(59.33,116.91) v1(59.4,10.59) v1(60.03,131.9) v1(60.03,130.88) v1(60.03,129.87) v1(60.74,120.75) v1(60.85,31.16) v1(61.04,131.9) v1(61.04,130.88) v1(61.04,129.87) v1(61.85,126.14) v1(62.12,198.09) v1(64.35,117.13) v1(65.99,157.18) v1(65.99,156.16) v1(65.99,155.15) v1(66.24,125.64) v1(67,157.18) v1(67,156.16) v1(67,155.15) v1(68.02,157.18) v1(68.02,156.16) v1(68.02,155.15) v1(69.6,54.9) v1(70.64,107.42) v1(71.67,10.85) v1(71.84,32.46) v1(73.76,134.12) v1(73.89,129.47) v1(74.3,39.7) v1(75.5,197.75) v1(77.03,188.03) v1(77.27,178.54) v1(80.78,32.43) v1(81.18,185.43) v1(81.64,136.63) v1(82.26,10.65) v1(85.15,87.89) v1(85.98,165.66) v1(85.98,163.12) v1(85.98,161.85) v1(85.98,160.58) v1(86.61,180.32) v1(86.59,178.9) v1(86.84,176.36) v1(87.25,165.66) v1(87.25,164.39) v1(87.25,163.12) v1(87.25,161.85) v1(87.25,160.58) v1(87.25,159.31) v1(87.2,121.62) v1(87.6,171.94) v1(87.66,173.21) v1(88.09,180.3) v1(88.06,178.88) v1(88.09,177.2) v1(88.54,175.8) v1(88.52,165.66) v1(88.52,164.39) v1(88.52,163.12) v1(88.52,161.85) v1(88.52,160.58) v1(88.52,159.31) v1(88.67,88.13) v1(88.85,173.97) v1(89.03,171.26) v1(89.1,172.42) v1(89.18,184.44) v1(89.46,180.3) v1(89.48,178.85) v1(89.71,182.86) v1(89.79,166.93) v1(89.79,165.66) v1(89.79,164.39) v1(89.79,163.12) v1(89.79,161.85) v1(89.79,160.58) v1(89.99,173.97) v1(90.12,175.83) v1(90.5,170.32) v1(90.58,184.41) v1(90.6,171.43) v1(91.06,165.66) v1(91.06,164.39) v1(91.06,163.12) v1(91.06,161.85) v1(91.06,160.58) v1(91.06,159.31) v1(91.36,178.24) v1(92.13,176.44) v1(92.18,174.84) v1(92.18,173.8) v1(92.33,165.66) v1(92.33,164.39) v1(92.33,163.12) v1(92.33,161.85) v1(92.33,160.58) v1(92.33,159.31) v1(92.38,183.45) v1(92.41,181.47) v1(92.35,110.73) v1(92.46,187.28) v1(92.52,10.47) v1(92.58,188.91) v1(92.84,178.24) v1(93.22,170.85) v1(93.6,164.39) v1(93.6,163.12) v1(93.6,161.85) v1(93.6,160.58) v1(93.71,86.71) v1(93.93,182.76) v1(94.11,188.88) v1(94.08,184.74) v1(94.13,176.46) v1(94.08,174.84) v1(94.08,173.52) v1(94.23,169.53) v1(94.67,171.81) v1(95.53,137.9) v1(95.58,188.96) v1(95.63,170.54) v1(95.73,187.54) v1(95.71,184.44) v1(96.04,176.44) v1(96.04,174.86) v1(96.04,173.52) v1(96.32,182.84) v1(96.6,178.44) v1(96.72,171.61) v1(96.72,144.87) v1(97.13,187.49) v1(97.21,188.96) v1(97.21,184.18) v1(97.33,67.32) v1(97.66,172.55) v1(97.94,173.82) v1(98.25,175.95) v1(98.29,88.46) v1(98.89,169.53) v1(99.11,182.08) v1(99.24,175.95) v1(99.29,180.2) v1(99.29,178.49) v1(100.61,183.47) v1(100.63,177.05) v1(100.71,181.31) v1(100.71,179.1) v1(100.69,22.12) v1(100.83,28.62) v1(100.83,12.2) v1(100.88,167.39) v1(101.03,91.26) v1(100.99,36.29) v1(101.13,172.87) v1(101.09,84.53) v1(101.13,74.9) v1(101.09,61.43) v1(101.1,54.17) v1(101.14,41.64) v1(101.16,100.22) v1(101.18,49.03) v1(101.26,189.37)
